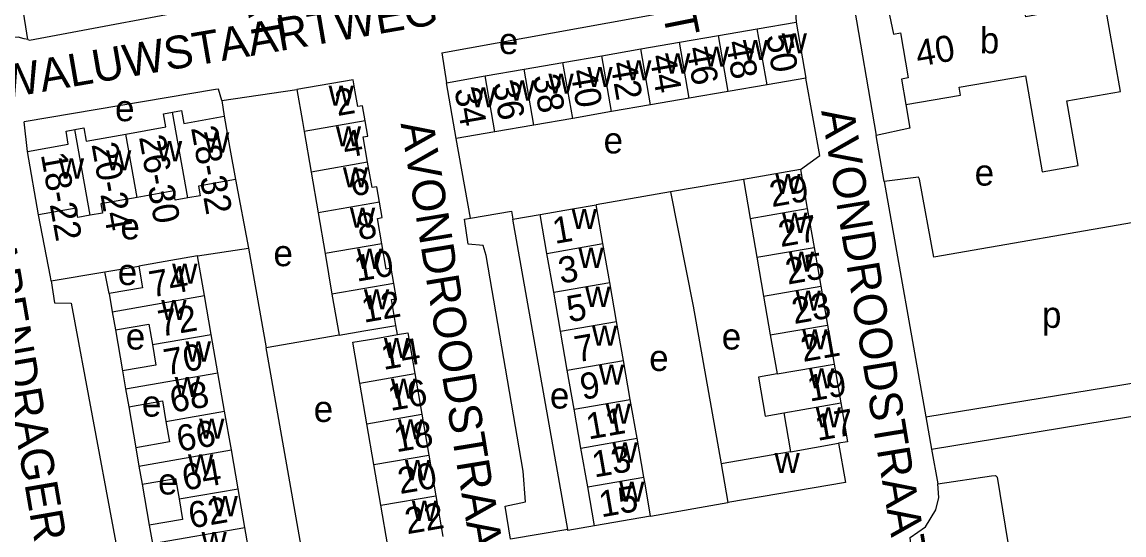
# Model space of a CAD drawing. Extents: x 162883 to 165538, y 383986 to 385172.
# Drawn here: x 164517.2 to 164685.6, y 384347.8 to 384426.2 of the extents above; entities that cross this region are included whole.
import ezdxf

# ---------------------------------------------------------------- set-up
doc = ezdxf.new("R2010")
doc.units = 0
for name, color, linetype in [('BLT_Basislijn', 7, 'Continuous'), ('BLT_Bebouwing', 7, 'Continuous'), ('BLT_Centroide', 7, 'Continuous'), ('BLT_Huisnummer', 7, 'Continuous'), ('BLT_Huisnummer_ tussenligend', 7, 'Continuous'), ('BLT_Huisnummer_reeks', 7, 'Continuous'), ('BLT_Onderverdeling_panden', 7, 'Continuous'), ('BLT_Straatnaam', 7, 'Continuous')]:
    doc.layers.add(name, color=color, linetype=linetype)

msp = doc.modelspace()

# ---------------------------------------------------------------- linework, layer by layer
at = {"layer": 'BLT_Basislijn'}
for p, q in [((164643.58, 384432.72), (164647.69, 384408.84)), ((164518.09, 384423.49), (164517.28, 384428.67)), ((164635.39, 384427.68), (164635.47, 384426.18)), ((164581.33, 384421.5), (164582.04, 384416.92)), ((164547.74, 384414.21), (164559.19, 384415.9)), ((164547.74, 384414.21), (164548.09, 384411.79)), ((164518.02, 384406.41), (164517.54, 384410.94)), ((164585.71, 384396.23), (164583.52, 384408.37)), ((164648.91, 384401.8), (164647.69, 384408.84)), ((164549.81, 384402.11), (164551.79, 384391.66)), ((164627.41, 384402.14), (164616.26, 384400.23)), ((164648.91, 384401.8), (164655.29, 384365.86)), ((164616.26, 384400.23), (164604.93, 384398.28)), ((164592.2, 384396.08), (164596.35, 384396.78)), ((164600.57, 384348.66), (164592.2, 384396.08)), ((164693.76, 384396.74), (164656.52, 384390.24)), ((164544.03, 384390.47), (164551.79, 384391.66)), ((164551.79, 384391.66), (164554.5, 384376.43)), ((164521.63, 384386.65), (164529.85, 384388.03)), ((164529.85, 384388.03), (164535.03, 384388.91)), ((164530.5, 384384.72), (164529.85, 384388.03)), ((164531.47, 384379.15), (164532.55, 384372.89)), ((164574.57, 384378.42), (164574.33, 384379.84)), ((164565.63, 384378.34), (164554.5, 384376.43)), ((164533.5, 384367.4), (164534.57, 384361.13)), ((164656.16, 384360.93), (164695.13, 384367.3)), ((164655.29, 384365.86), (164656.16, 384360.93)), ((164656.16, 384360.93), (164657.1, 384355.64)), ((164535.54, 384355.56), (164536.64, 384349.31)), ((164613.24, 384350.69), (164625.02, 384352.76))]:
    msp.add_line(p, q, dxfattribs=at)
for points in [[(164518.09, 384423.49), (164518.32, 384423.43), (164548.26, 384429.02), (164547.12, 384434.04)], [(164581.33, 384421.5), (164632.05, 384430.72), (164634.45, 384430.83), (164635.39, 384427.68)], [(164518.09, 384423.49), (164517.54, 384423.64), (164516.61, 384423.88), (164506.01, 384422.91)], [(164636.14, 384403.65), (164639.11, 384405.77), (164636.95, 384417.63)], [(164547.74, 384414.21), (164547.24, 384415.91), (164546.76, 384415.86), (164517.54, 384410.94)], [(164652.23, 384413.57), (164652.85, 384409.99), (164647.69, 384408.84)], [(164656.52, 384390.24), (164654.34, 384402.18), (164654.18, 384402.5), (164648.91, 384401.8)], [(164616.26, 384400.23), (164619.74, 384382.75), (164623.99, 384358.7)], [(164521.63, 384386.65), (164521.53, 384387.24), (164519.74, 384396.73)], [(164600.57, 384348.66), (164591.85, 384347.2), (164591.02, 384352.23), (164594.12, 384352.88), (164593.76, 384357.55), (164588.13, 384390.49), (164587.65, 384392.03), (164585.37, 384392.25), (164584.78, 384396.07), (164585.71, 384396.23)], [(164585.71, 384396.23), (164591.99, 384397.27), (164592.2, 384396.08)], [(164655.29, 384365.86), (164698.02, 384372.84), (164693.76, 384396.74)], [(164521.63, 384386.65), (164522.18, 384383.28), (164524.71, 384383.24), (164534.32, 384331.61), (164534.39, 384328.75), (164533.41, 384324.89)], [(164563.35, 384331.56), (164562.44, 384331.4), (164554.6, 384375.83), (164554.5, 384376.43)], [(164653.04, 384345.86), (164652.89, 384347.44), (164655.23, 384349.05), (164656.79, 384351.65), (164657.29, 384353.54), (164657.1, 384355.64)], [(164657.1, 384355.64), (164665.31, 384356.86), (164665.95, 384356.9), (164666.17, 384356.65), (164671, 384327.01)], [(164604.66, 384349.2), (164600.6, 384348.48), (164600.57, 384348.66)]]:
    msp.add_lwpolyline(points, dxfattribs=at)
at = {"layer": 'BLT_Bebouwing'}
for p, q in [((164629.54, 384425.15), (164635.47, 384426.18)), ((164635.47, 384426.18), (164636.95, 384417.63)), ((164623.6, 384424.12), (164629.54, 384425.15)), ((164611.73, 384422.07), (164617.66, 384423.1)), ((164617.66, 384423.1), (164623.6, 384424.12)), ((164605.79, 384421.04), (164611.73, 384422.07)), ((164593.92, 384418.98), (164599.85, 384420.01)), ((164599.85, 384420.01), (164605.79, 384421.04)), ((164582.04, 384416.92), (164587.98, 384417.95)), ((164587.98, 384417.95), (164593.92, 384418.98)), ((164583.52, 384408.37), (164582.04, 384416.92)), ((164631.02, 384416.6), (164625.08, 384415.57)), ((164636.95, 384417.63), (164631.02, 384416.6)), ((164619.14, 384414.55), (164613.21, 384413.52)), ((164625.08, 384415.57), (164619.14, 384414.55)), ((164613.21, 384413.52), (164607.27, 384412.49)), ((164601.33, 384411.46), (164595.4, 384410.43)), ((164607.27, 384412.49), (164601.33, 384411.46)), ((164560.29, 384409.47), (164561.35, 384403.27)), ((164589.46, 384409.4), (164583.52, 384408.37)), ((164595.4, 384410.43), (164589.46, 384409.4)), ((164519.74, 384396.73), (164518.02, 384406.41)), ((164561.35, 384403.27), (164562.42, 384397.05)), ((164636.14, 384403.65), (164637.17, 384397.7)), ((164627.41, 384402.14), (164628.43, 384396.19)), ((164605.96, 384392.33), (164604.93, 384398.28)), ((164637.17, 384397.7), (164638.2, 384391.76)), ((164562.42, 384397.05), (164563.49, 384390.81)), ((164597.39, 384390.84), (164596.35, 384396.78)), ((164628.43, 384396.19), (164629.46, 384390.25)), ((164563.49, 384390.81), (164564.55, 384384.61)), ((164598.43, 384384.89), (164597.39, 384390.84)), ((164607, 384386.39), (164605.96, 384392.33)), ((164638.2, 384391.76), (164639.22, 384385.82)), ((164545.08, 384384.38), (164544.03, 384390.47)), ((164629.46, 384390.25), (164630.49, 384384.31)), ((164608.04, 384380.44), (164607, 384386.39)), ((164639.22, 384385.82), (164640.25, 384379.88)), ((164530.5, 384384.72), (164530.98, 384381.93)), ((164546.11, 384378.47), (164545.08, 384384.38)), ((164564.55, 384384.61), (164565.63, 384378.34)), ((164599.47, 384378.94), (164598.43, 384384.89)), ((164630.49, 384384.31), (164631.52, 384378.37)), ((164530.98, 384381.93), (164531.47, 384379.15)), ((164609.08, 384374.49), (164608.04, 384380.44)), ((164640.25, 384379.88), (164641.28, 384373.93)), ((164547.13, 384372.59), (164546.11, 384378.47)), ((164600.51, 384372.99), (164599.47, 384378.94)), ((164631.52, 384378.37), (164632.55, 384372.43)), ((164610.12, 384368.54), (164609.08, 384374.49)), ((164641.28, 384373.93), (164642.31, 384367.99)), ((164532.55, 384372.89), (164533.03, 384370.14)), ((164548.15, 384366.72), (164547.13, 384372.59)), ((164577.23, 384372.47), (164578.29, 384366.25)), ((164601.55, 384367.04), (164600.51, 384372.99)), ((164569.89, 384364.8), (164568.82, 384371.03)), ((164533.03, 384370.14), (164533.5, 384367.4)), ((164611.16, 384362.59), (164610.12, 384368.54)), ((164549.18, 384360.8), (164548.15, 384366.72)), ((164578.29, 384366.25), (164579.36, 384360.03)), ((164602.59, 384361.1), (164601.55, 384367.04)), ((164633.57, 384366.48), (164634.6, 384360.54)), ((164570.95, 384358.58), (164569.89, 384364.8)), ((164612.2, 384356.65), (164611.16, 384362.59)), ((164534.57, 384361.13), (164535.06, 384358.34)), ((164550.21, 384354.89), (164549.18, 384360.8)), ((164603.62, 384355.15), (164602.59, 384361.1)), ((164634.6, 384360.54), (164623.99, 384358.7)), ((164579.36, 384360.03), (164580.43, 384353.8)), ((164535.06, 384358.34), (164535.54, 384355.56)), ((164572.02, 384352.36), (164570.95, 384358.58)), ((164623.99, 384358.7), (164625.02, 384352.76)), ((164551.24, 384348.96), (164550.21, 384354.89)), ((164580.43, 384353.8), (164581.49, 384347.58)), ((164604.66, 384349.2), (164603.62, 384355.15)), ((164573.09, 384346.14), (164572.02, 384352.36)), ((164613.24, 384350.69), (164604.66, 384349.2)), ((164536.64, 384349.31), (164537.12, 384346.51)), ((164552.27, 384343.05), (164551.24, 384348.96))]:
    msp.add_line(p, q, dxfattribs=at)
for points in [[(164652.23, 384413.57), (164660.6, 384415.03), (164660.39, 384416.21), (164670.49, 384417.97), (164673.04, 384403.31), (164678.55, 384404.27), (164676.82, 384414.15), (164685.03, 384415.58), (164682.45, 384430.29), (164673.95, 384428.76), (164674.15, 384427.63), (164670.54, 384426.98), (164669.33, 384433.92)], [(164649.52, 384428.22), (164650.35, 384424.35), (164651.39, 384424.53), (164652.61, 384417.67), (164651.55, 384417.48), (164652.23, 384413.57)], [(164568.1, 384415.51), (164567.78, 384417.37), (164559.19, 384415.9)], [(164559.19, 384415.9), (164560.03, 384410.97), (164560.29, 384409.47)], [(164569.64, 384411.07), (164569.24, 384413.4), (164568.48, 384413.27), (164568.1, 384415.51)], [(164540.18, 384412.42), (164541.57, 384412.67), (164541.92, 384410.69), (164548.09, 384411.79)], [(164533.08, 384409.07), (164539.17, 384410.16), (164538.81, 384412.18), (164540.18, 384412.42)], [(164548.09, 384411.79), (164548.96, 384406.86), (164549.81, 384402.11)], [(164570, 384404.76), (164569.34, 384408.63), (164570.04, 384408.75), (164569.64, 384411.07)], [(164518.02, 384406.41), (164524.27, 384407.52), (164523.92, 384409.53), (164525.27, 384409.77)], [(164525.27, 384409.77), (164526.65, 384410.02), (164527.01, 384407.99), (164533.08, 384409.07)], [(164571.82, 384398.66), (164571.41, 384401.01), (164570.67, 384400.88), (164570, 384404.76)], [(164636.14, 384403.65), (164631.21, 384402.79), (164627.41, 384402.14)], [(164549.81, 384402.11), (164544.14, 384401.1), (164544.4, 384399.63), (164542.51, 384399.3)], [(164534.8, 384399.39), (164529.23, 384398.4), (164529.47, 384397), (164527.61, 384396.67)], [(164542.51, 384399.3), (164540.62, 384398.96), (164540.37, 384400.38), (164534.8, 384399.39)], [(164527.61, 384396.67), (164525.74, 384396.34), (164525.49, 384397.75), (164519.74, 384396.73)], [(164572.18, 384392.3), (164571.52, 384396.18), (164572.22, 384396.3), (164571.82, 384398.66)], [(164596.35, 384396.78), (164601.28, 384397.65), (164604.93, 384398.28)], [(164574, 384386.23), (164573.6, 384388.56), (164572.85, 384388.43), (164572.18, 384392.3)], [(164544.03, 384390.47), (164539.96, 384389.76), (164535.03, 384388.91)], [(164535.03, 384388.91), (164535.6, 384385.6), (164530.5, 384384.72)], [(164574.33, 384379.84), (164573.65, 384383.78), (164574.4, 384383.91), (164574, 384386.23)], [(164531.47, 384379.15), (164536.58, 384380.03), (164537.12, 384376.91)], [(164565.63, 384378.34), (164569.4, 384378.99), (164574.33, 384379.84)], [(164568.82, 384371.03), (164567.75, 384377.25), (164571.23, 384377.84), (164574.57, 384378.42)], [(164574.57, 384378.42), (164576.16, 384378.69), (164577.23, 384372.47)], [(164537.12, 384376.91), (164537.66, 384373.78), (164532.55, 384372.89)], [(164632.55, 384372.43), (164629.72, 384371.93), (164630.75, 384365.98), (164633.57, 384366.48)], [(164533.5, 384367.4), (164538.64, 384368.29), (164539.18, 384365.16)], [(164642.31, 384367.99), (164643.33, 384362.07), (164641.96, 384361.83)], [(164539.18, 384365.16), (164539.72, 384362.03), (164534.57, 384361.13)], [(164641.96, 384361.83), (164642.99, 384355.85), (164625.02, 384352.76)], [(164535.54, 384355.56), (164540.65, 384356.44), (164541.2, 384353.32)], [(164613.24, 384350.69), (164612.38, 384355.62), (164612.2, 384356.65)], [(164541.2, 384353.32), (164541.74, 384350.19), (164536.64, 384349.31)]]:
    msp.add_lwpolyline(points, dxfattribs=at)
at = {"layer": 'BLT_Onderverdeling_panden'}
for p, q in [((164631.02, 384416.6), (164629.54, 384425.15)), ((164619.14, 384414.55), (164617.66, 384423.1)), ((164625.08, 384415.57), (164623.6, 384424.12)), ((164613.21, 384413.52), (164611.73, 384422.07)), ((164601.33, 384411.46), (164599.85, 384420.01)), ((164607.27, 384412.49), (164605.79, 384421.04)), ((164589.46, 384409.4), (164587.98, 384417.95)), ((164595.4, 384410.43), (164593.92, 384418.98)), ((164542.51, 384399.3), (164540.18, 384412.42)), ((164569.64, 384411.07), (164560.29, 384409.47)), ((164527.61, 384396.67), (164525.27, 384409.77)), ((164534.8, 384399.39), (164533.08, 384409.07)), ((164570, 384404.76), (164561.35, 384403.27)), ((164571.82, 384398.66), (164562.42, 384397.05)), ((164628.43, 384396.19), (164637.17, 384397.7)), ((164572.18, 384392.3), (164563.49, 384390.81)), ((164597.39, 384390.84), (164605.96, 384392.33)), ((164629.46, 384390.25), (164638.2, 384391.76)), ((164574, 384386.23), (164564.55, 384384.61)), ((164598.43, 384384.89), (164607, 384386.39)), ((164630.49, 384384.31), (164639.22, 384385.82)), ((164530.98, 384381.93), (164545.08, 384384.38)), ((164599.47, 384378.94), (164608.04, 384380.44)), ((164631.52, 384378.37), (164640.25, 384379.88)), ((164537.12, 384376.91), (164546.11, 384378.47)), ((164600.51, 384372.99), (164609.08, 384374.49)), ((164632.55, 384372.43), (164641.28, 384373.93)), ((164533.03, 384370.14), (164547.13, 384372.59)), ((164568.82, 384371.03), (164577.23, 384372.47)), ((164601.55, 384367.04), (164610.12, 384368.54)), ((164633.57, 384366.48), (164642.31, 384367.99)), ((164539.18, 384365.16), (164548.15, 384366.72)), ((164569.89, 384364.8), (164578.29, 384366.25)), ((164602.59, 384361.1), (164611.16, 384362.59)), ((164535.06, 384358.34), (164549.18, 384360.8)), ((164634.6, 384360.54), (164641.96, 384361.83)), ((164570.95, 384358.58), (164579.36, 384360.03)), ((164603.62, 384355.15), (164612.2, 384356.65)), ((164541.2, 384353.32), (164550.21, 384354.89)), ((164572.02, 384352.36), (164580.43, 384353.8)), ((164625.01, 384352.76), (164625.02, 384352.74)), ((164537.12, 384346.51), (164551.24, 384348.96))]:
    msp.add_line(p, q, dxfattribs=at)

# ---------------------------------------------------------------- texts
at = {"layer": 'BLT_Centroide'}
for s, p in [('e', (164590.06, 384421.29)), ('w', (164633.25, 384421.39)), ('b', (164663.53, 384421.39)), ('w', (164627.31, 384420.38)), ('w', (164615.44, 384418.31)), ('w', (164621.38, 384419.34)), ('w', (164609.5, 384417.28)), ('w', (164597.62, 384415.22)), ('w', (164603.56, 384416.25)), ('w', (164564.03, 384413.41)), ('w', (164585.75, 384413.16)), ('w', (164591.69, 384414.19)), ('e', (164531.41, 384411.03)), ('w', (164545, 384406.25)), ('w', (164565.14, 384407.19)), ('w', (164537.8, 384404.92)), ('e', (164606.05, 384406.11)), ('w', (164530.03, 384403.53)), ('w', (164522.81, 384402.27)), ('e', (164662.74, 384401.19)), ('w', (164566.22, 384400.91)), ('w', (164632.29, 384399.91)), ('w', (164567.29, 384394.75)), ('w', (164601.16, 384394.56)), ('e', (164532.23, 384392.98)), ('w', (164633.31, 384393.97)), ('e', (164555.61, 384388.88)), ('w', (164568.37, 384388.47)), ('w', (164602.2, 384388.62)), ('w', (164634.34, 384388.03)), ('e', (164531.82, 384386)), ('w', (164540.13, 384386.19)), ('w', (164603.23, 384382.66)), ('w', (164569.43, 384382.28)), ('w', (164635.37, 384382.09)), ('w', (164538.47, 384380.66)), ('p', (164673.02, 384379.46)), ('e', (164533.05, 384376.15)), ('w', (164604.27, 384376.72)), ('e', (164624.1, 384376.15)), ('w', (164636.4, 384376.16)), ('w', (164542.2, 384374.31)), ('w', (164572.48, 384374.84)), ('e', (164613.02, 384372.87)), ('w', (164605.31, 384370.78)), ('w', (164637.42, 384370.22)), ('w', (164540.52, 384368.88)), ('w', (164573.56, 384368.62)), ('e', (164535.52, 384365.9)), ('e', (164597.85, 384367.13)), ('e', (164561.76, 384365.08)), ('w', (164606.35, 384364.81)), ('w', (164638.45, 384364.25)), ('w', (164544.26, 384362.53)), ('w', (164574.62, 384362.41)), ('w', (164607.39, 384358.88)), ('w', (164542.55, 384357.06)), ('w', (164575.69, 384356.19)), ('w', (164632.16, 384357.28)), ('e', (164537.98, 384354)), ('w', (164608.43, 384352.91)), ('w', (164546.3, 384350.69)), ('w', (164576.75, 384349.97)), ('w', (164544.62, 384345.22))]:
    msp.add_text(s, height=4, dxfattribs=at).set_placement(p)
at = {"layer": 'BLT_Huisnummer'}
for s, rotation, p in [('50', 279.8271, (164630.84, 384424.1)), ('40', 9.8917, (164654.1, 384419.35)), ('46', 279.8271, (164618.7, 384422.16)), ('42', 279.8271, (164607.07, 384419.88)), ('38', 279.8271, (164595.22, 384417.91)), ('2', 9.7263, (164565.38, 384411.81)), ('34', 279.8271, (164583.25, 384415.88)), ('6', 9.7263, (164567.64, 384399.5)), ('29', 9.9693, (164631.76, 384397.89)), ('1', 9.905, (164598.61, 384392.27)), ('25', 9.9693, (164634.19, 384386.06)), ('74', 9.8586, (164536.98, 384384.09)), ('12', 9.7263, (164569.42, 384380.23)), ('5', 9.905, (164600.77, 384380.3)), ('21', 9.9693, (164636.54, 384374.24)), ('14', 9.7263, (164572.42, 384373.02)), ('9', 9.905, (164602.83, 384368.44)), ('68', 9.8586, (164540.15, 384366.47)), ('17', 9.9693, (164638.73, 384362.18)), ('18', 9.7263, (164574.38, 384360.44)), ('64', 9.8586, (164542.02, 384354.57)), ('15', 9.905, (164605.7, 384350.5)), ('22', 9.7263, (164576.04, 384347.92))]:
    msp.add_text(s, height=4, rotation=rotation, dxfattribs=at).set_placement(p)
at = {"layer": 'BLT_Huisnummer_ tussenligend'}
for s, rotation, p in [('48', 279.8271, (164624.7, 384423.09)), ('44', 279.8271, (164613.06, 384420.96)), ('40', 279.8271, (164600.95, 384418.71)), ('36', 279.8271, (164589.11, 384416.81)), ('4', 9.7263, (164566.57, 384405.41)), ('8', 9.7263, (164568.71, 384392.83)), ('27', 9.9693, (164633.11, 384391.79)), ('10', 9.7263, (164568.34, 384386.5)), ('3', 9.905, (164599.5, 384386.19)), ('23', 9.9693, (164635.16, 384380.03)), ('72', 9.8586, (164538.34, 384378.09)), ('7', 9.905, (164601.96, 384374.17)), ('70', 9.8586, (164539.21, 384372.19)), ('19', 9.9693, (164637.54, 384368.18)), ('16', 9.7263, (164573.48, 384366.75)), ('11', 9.905, (164603.74, 384362.39)), ('66', 9.8586, (164541.18, 384360.51)), ('13', 9.905, (164604.63, 384356.58)), ('20', 9.7263, (164574.95, 384354.06)), ('62', 9.8586, (164542.99, 384348.79))]:
    msp.add_text(s, height=4, rotation=rotation, dxfattribs=at).set_placement(p)
at = {"layer": 'BLT_Huisnummer_reeks'}
for s, rotation, p in [('28-32', 280.0834, (164543.01, 384410.02)), ('20-24', 280.093, (164527.8, 384407.5)), ('26-30', 280.0823, (164535.06, 384408.62)), ('18-22', 280.089, (164520.06, 384405.95))]:
    msp.add_text(s, height=4, rotation=rotation, dxfattribs=at).set_placement(p)
at = {"layer": 'BLT_Straatnaam'}
for s, height, rotation, p in [('MORGENROODSTRAAT', 5, 281.2005, (164600.99, 384498.66)), ('MORGENROODSTRAAT', 4.9999, 279.8684, (164539.45, 384498.09)), ('ZWALUWSTAARTWEG', 5, 9.7726, (164510.03, 384413.72)), ('AVONDROODSTRAAT', 5, 279.3314, (164639.29, 384412.6)), ('AVONDROODSTRAAT', 5, 279.3314, (164575.03, 384410.67)), ('WAPENDRAGERSTRAAT', 5, 279.8251, (164510.08, 384398.83))]:
    msp.add_text(s, height=height, rotation=rotation, dxfattribs=at).set_placement(p)

doc.saveas('drawing.dxf')
